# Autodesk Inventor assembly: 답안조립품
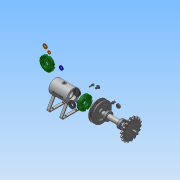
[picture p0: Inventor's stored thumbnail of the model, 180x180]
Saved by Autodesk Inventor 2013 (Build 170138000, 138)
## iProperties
Created: 2016-03
Part Number: 답안조립품
Document SubType Name: Assembly
Designer: Administrator
Author: Administrator
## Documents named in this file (16)
- C:\Users\Administrator\Desktop\460308V1016\답안조립품.iam
- C:\Users\Administrator\Desktop\460308V1016\본체.ipt
- C:\Users\Administrator\Desktop\460308V1016\V벨트풀리.ipt
- C:\Users\Administrator\Desktop\460308V1016\너트 M 8.ipt
- C:\Users\Administrator\Desktop\460308V1016\니플 M 6 x 0.75.ipt
- C:\Users\Administrator\Desktop\460308V1016\베어링 15 x 32 x 9.ipt
- C:\Users\Administrator\Desktop\460308V1016\볼트 M 6 x 8.ipt
- C:\Users\Administrator\Desktop\460308V1016\볼트 M4 x 12.ipt
- C:\Users\Administrator\Desktop\460308V1016\스프로킷.ipt
- C:\Users\Administrator\Desktop\460308V1016\스프링와셔 8.ipt
- C:\Users\Administrator\Desktop\460308V1016\오일 실 15 25 7.ipt
- C:\Users\Administrator\Desktop\460308V1016\와셔 6x11.5.ipt
- C:\Users\Administrator\Desktop\460308V1016\와셔 8x17.ipt
- C:\Users\Administrator\Desktop\460308V1016\축.ipt
- C:\Users\Administrator\Desktop\460308V1016\커버.ipt
- C:\Users\Administrator\Desktop\460308V1016\키 3 x 3 x 12.ipt
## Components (4 placed, 3 different names)
1. V벨트풀리:1
2. KS B 2023 6002 - 15 x 32 x 9:1
3. ISO 4762 M4 x 12:1
4. KS B 2023 6002 - 15 x 32 x 9:2
